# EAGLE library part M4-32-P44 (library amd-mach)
AMD MACH SERIES
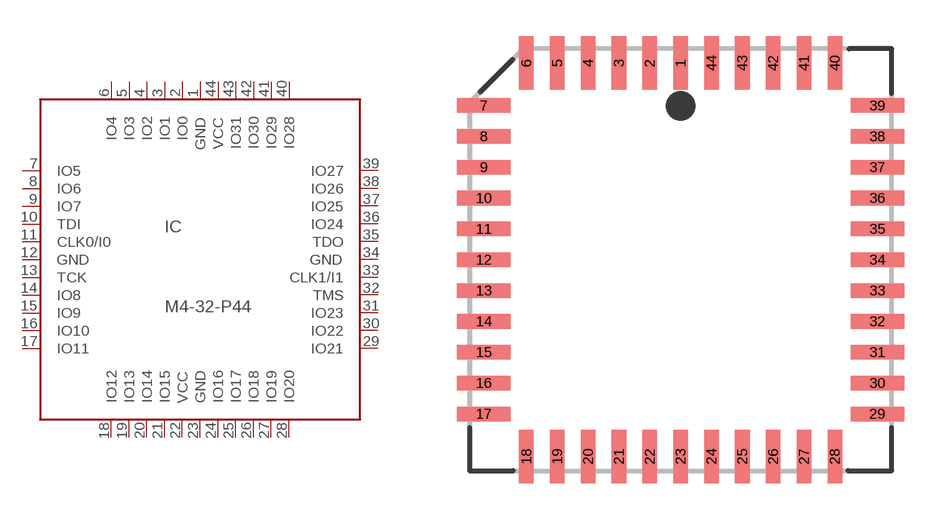
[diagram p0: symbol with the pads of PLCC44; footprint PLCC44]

Designator prefix IC

## M4-32-P44 (OC_FARNELL: unknown; OC_NEWARK: unknown)  [PLCC44]
1  GND  pwr
2  IO0
3  IO1
4  IO2
5  IO3
6  IO4
7  IO5
8  IO6
9  IO7
10  TDI  in
11  CLK0/I0  in
12  GND  pwr
13  TCK  in
14  IO8
15  IO9
16  IO10
17  IO11
18  IO12
19  IO13
20  IO14
21  IO15
22  VCC  pwr
23  GND  pwr
24  IO16
25  IO17
26  IO18
27  IO19
28  IO20
29  IO21
30  IO22
31  IO23
32  TMS  in
33  CLK1/I1  in
34  GND  pwr
35  TDO  out
36  IO24
37  IO25
38  IO26
39  IO27
40  IO28
41  IO29
42  IO30
43  IO31
44  VCC  pwr

## Footprint PLCC44 (pad centres in mm)
PLASTIC LEADED CHIP CARRIER
smd 0.6 x 2.2: 1 0,8.1; 2 -1.27,8.1; 3 -2.54,8.1; 4 -3.81,8.1; 5 -5.08,8.1; 6 -6.35,8.1; 18 -6.35,-8.1; 19 -5.08,-8.1; 20 -3.81,-8.1; 21 -2.54,-8.1; 22 -1.27,-8.1; 23 0,-8.1; 24 1.27,-8.1; 25 2.54,-8.1; 26 3.81,-8.1; 27 5.08,-8.1; 28 6.35,-8.1; 40 6.35,8.1; 41 5.08,8.1; 42 3.81,8.1; 43 2.54,8.1; 44 1.27,8.1
smd 2.2 x 0.6: 7 -8.1,6.35; 8 -8.1,5.08; 9 -8.1,3.81; 10 -8.1,2.54; 11 -8.1,1.27; 12 -8.1,0; 13 -8.1,-1.27; 14 -8.1,-2.54; 15 -8.1,-3.81; 16 -8.1,-5.08; 17 -8.1,-6.35; 29 8.1,-6.35; 30 8.1,-5.08; 31 8.1,-3.81; 32 8.1,-2.54; 33 8.1,-1.27; 34 8.1,0; 35 8.1,1.27; 36 8.1,2.54; 37 8.1,3.81; 38 8.1,5.08; 39 8.1,6.35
